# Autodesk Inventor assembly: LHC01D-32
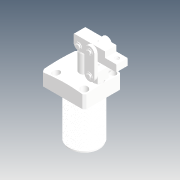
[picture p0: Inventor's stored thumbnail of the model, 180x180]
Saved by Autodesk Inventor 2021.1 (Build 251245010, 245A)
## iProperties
Created: 2019-04
Part Number: LHC01D-32
Description: STEP AP214
Document SubType Name: Assembly
Designer: user
Title: LHC01D-32.STEP
Revision Number: ÈÎºÎ
Sending System: SolidWorks 2016
Preprocessor: SwSTEP 2.0
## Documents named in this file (12)
- D:\Vault_2016\Projekty\Clamptek\Hydraulic\LHC01D\Inventor\LHC01D-32\LHC01D-32.iam
- D:\Vault_2016\Projekty\Clamptek\Hydraulic\LHC01D\Inventor\LHC01D-32\LHC01D-32-07.ipt
- D:\Vault_2016\Projekty\Clamptek\Hydraulic\LHC01D\Inventor\LHC01D-32\LHC01D32»îÈû¸Ë.ipt
- D:\Vault_2016\Projekty\Clamptek\Hydraulic\LHC01D\Inventor\LHC01D-32\CPLCU-32ZCK.ipt
- D:\Vault_2016\Projekty\Clamptek\Hydraulic\LHC01D\Inventor\LHC01D-32\CPLCU-32YB.ipt
- D:\Vault_2016\Projekty\Clamptek\Hydraulic\LHC01D\Inventor\LHC01D-32\CPLCU-32LG.ipt
- D:\Vault_2016\Projekty\Clamptek\Hydraulic\LHC01D\Inventor\LHC01D-32\CPLCU-32DX.ipt
- D:\Vault_2016\Projekty\Clamptek\Hydraulic\LHC01D\Inventor\LHC01D-32\CPLCU-32X.ipt
- D:\Vault_2016\Projekty\Clamptek\Hydraulic\LHC01D\Inventor\LHC01D-32\LHC01D-32-08.ipt
- D:\Vault_2016\Projekty\Clamptek\Hydraulic\LHC01D\Inventor\LHC01D-32\LHC01D-32-01_3.ipt
- D:\Vault_2016\Projekty\Clamptek\Hydraulic\LHC01D\Inventor\LHC01D-32\M4ningjin_3.ipt
- D:\Vault_2016\Projekty\Clamptek\Hydraulic\LHC01D\Inventor\LHC01D-32\¶ÂÍ·_3.ipt
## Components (24 placed, 24 different names)
1. LHC01D-32-07_1
2. LHC01D32»îÈû¸Ë_2
3. CPLCU-32ZCK_3
4. CPLCU-32YB_4
5. CPLCU-32LG_5
6. CPLCU-32LG_6
7. CPLCU-32DX_7
8. CPLCU-32X_8
9. CPLCU-32X_9
10. LHC01D-32-08_10
11. LHC01D-32-08_11
12. LHC01D-32-08_12
13. LHC01D-32-08_13
14. LHC01D-32-08_14
15. LHC01D-32-08_15
16. LHC01D-32-01_3_16
17. LHC01D-32-01_3_17
18. LHC01D-32-01_3_18
19. LHC01D-32-01_3_19
20. LHC01D-32-01_3_20
21. LHC01D-32-01_3_21
22. M4ningjin_3_22
23. ¶ÂÍ·_3_23
24. ¶ÂÍ·_3_24
